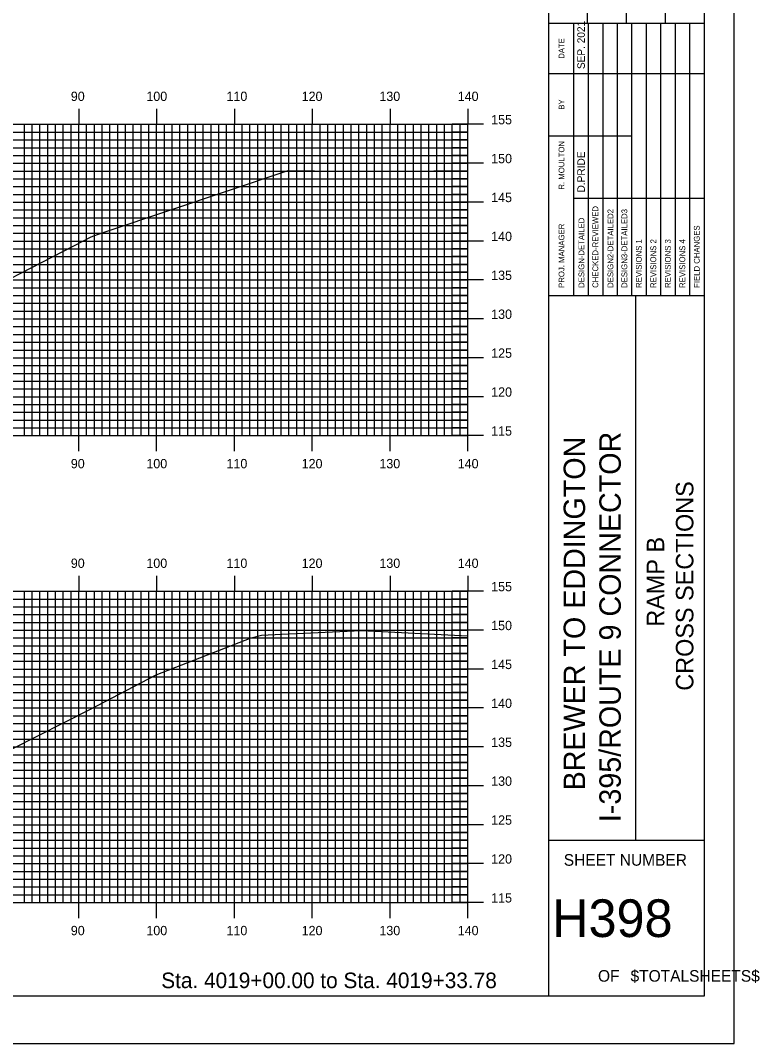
# Model space of a CAD drawing. Extents: x 854902 to 855245, y 364661 to 364881.
# Drawn here: x 855149.8 to 855244.8, y 364661.3 to 364792.7 of the extents above; entities that cross this region are included whole.
import ezdxf

# ---------------------------------------------------------------- set-up
doc = ezdxf.new("R2010")
doc.units = 0
for name, color, linetype in [('BORDER', 7, 'Continuous'), ('H_V ANNOTATION', 7, 'Continuous'), ('MAJOR', 7, 'Continuous'), ('MINOR', 7, 'Continuous'), ('PLOT BOUNDARY', 7, 'Continuous'), ('S_Roadway_Centerline', 7, 'Continuous')]:
    doc.layers.add(name, color=color, linetype=linetype)

msp = doc.modelspace()

# ---------------------------------------------------------------- linework, layer by layer
at = {"layer": 'BORDER'}
for p, q in [((855217.75, 364667.37), (855217.75, 364877.37)), ((855222.75, 364792.38), (855222.75, 364809.67)), ((855227.75, 364792.38), (855227.75, 364809.67)), ((855232.75, 364792.38), (855232.75, 364809.67)), ((855217.75, 364792.38), (855237.75, 364792.38)), ((855217.75, 364757.38), (855237.75, 364757.38)), ((855228.93, 364687.38), (855228.93, 364757.38)), ((855217.75, 364687.38), (855237.75, 364687.38))]:
    msp.add_line(p, q, dxfattribs=at)
msp.add_lwpolyline([(854917.75, 364667.37), (855237.75, 364667.37), (855237.75, 364877.37), (854917.75, 364877.37)], close=True, dxfattribs=at)
for points in [[(855220.98, 364785.88), (855220.98, 364792.38)], [(855222.84, 364757.38), (855222.84, 364792.38)], [(855224.71, 364792.38), (855224.71, 364757.38)], [(855226.57, 364757.38), (855226.57, 364792.38)], [(855228.43, 364757.38), (855228.43, 364792.38)], [(855230.3, 364757.38), (855230.3, 364792.38)], [(855232.16, 364757.38), (855232.16, 364792.38)], [(855234.02, 364757.38), (855234.02, 364792.38)], [(855235.89, 364757.38), (855235.89, 364792.38)], [(855220.98, 364757.38), (855220.98, 364790.96)], [(855217.75, 364785.88), (855237.75, 364785.88)], [(855217.75, 364777.88), (855220.98, 364777.88)], [(855220.98, 364777.88), (855228.43, 364777.88)], [(855220.98, 364769.88), (855237.75, 364769.88)]]:
    msp.add_lwpolyline(points, dxfattribs=at)
at = {"layer": 'MAJOR'}
for p, q in [((855157.35, 364781.37), (855157.35, 364779.37)), ((855167.35, 364781.37), (855167.35, 364779.37)), ((855177.35, 364781.37), (855177.35, 364779.37)), ((855187.35, 364781.37), (855187.35, 364779.37)), ((855197.35, 364781.37), (855197.35, 364779.37)), ((855207.35, 364781.37), (855207.35, 364779.37)), ((854927.35, 364779.37), (855207.35, 364779.37)), ((854927.35, 364779.37), (855207.35, 364779.37)), ((855157.35, 364739.37), (855157.35, 364779.37)), ((855167.35, 364739.37), (855167.35, 364779.37)), ((855177.35, 364739.37), (855177.35, 364779.37)), ((855187.35, 364739.37), (855187.35, 364779.37)), ((855197.35, 364739.37), (855197.35, 364779.37)), ((855209.35, 364779.37), (855205.34, 364779.37)), ((855207.35, 364739.37), (855207.35, 364779.37)), ((855207.35, 364739.37), (855207.35, 364779.37)), ((854927.35, 364774.37), (855207.35, 364774.37)), ((855209.35, 364774.37), (855205.34, 364774.37)), ((854927.35, 364769.37), (855207.35, 364769.37)), ((855209.35, 364769.37), (855205.34, 364769.37)), ((854927.35, 364764.37), (855207.35, 364764.37)), ((855209.35, 364764.37), (855205.34, 364764.37)), ((854927.35, 364759.37), (855207.35, 364759.37)), ((855209.35, 364759.37), (855205.34, 364759.37)), ((854927.35, 364754.37), (855207.35, 364754.37)), ((855209.35, 364754.37), (855205.34, 364754.37)), ((854927.35, 364749.37), (855207.35, 364749.37)), ((855209.35, 364749.37), (855205.34, 364749.37)), ((854927.35, 364744.37), (855207.35, 364744.37)), ((855209.35, 364744.37), (855205.34, 364744.37)), ((854927.35, 364739.37), (855207.35, 364739.37)), ((854927.35, 364739.37), (855207.35, 364739.37)), ((855157.35, 364737.37), (855157.35, 364739.37)), ((855167.35, 364737.37), (855167.35, 364739.37)), ((855177.35, 364737.37), (855177.35, 364739.37)), ((855187.35, 364737.37), (855187.35, 364739.37)), ((855197.35, 364737.37), (855197.35, 364739.37)), ((855209.35, 364739.37), (855205.34, 364739.37)), ((855207.35, 364737.37), (855207.35, 364739.37)), ((855157.35, 364721.37), (855157.35, 364719.37)), ((855167.35, 364721.37), (855167.35, 364719.37)), ((855177.35, 364721.37), (855177.35, 364719.37)), ((855187.35, 364721.37), (855187.35, 364719.37)), ((855197.35, 364721.37), (855197.35, 364719.37)), ((855207.35, 364721.37), (855207.35, 364719.37)), ((854927.35, 364719.37), (855207.35, 364719.37)), ((854927.35, 364719.37), (855207.35, 364719.37)), ((855157.35, 364679.37), (855157.35, 364719.37)), ((855167.35, 364679.37), (855167.35, 364719.37)), ((855177.35, 364679.37), (855177.35, 364719.37)), ((855187.35, 364679.37), (855187.35, 364719.37)), ((855197.35, 364679.37), (855197.35, 364719.37)), ((855209.35, 364719.37), (855205.34, 364719.37)), ((855207.35, 364679.37), (855207.35, 364719.37)), ((855207.35, 364679.37), (855207.35, 364719.37)), ((854927.35, 364714.37), (855207.35, 364714.37)), ((855209.35, 364714.37), (855205.34, 364714.37)), ((854927.35, 364709.37), (855207.35, 364709.37)), ((855209.35, 364709.37), (855205.34, 364709.37)), ((854927.35, 364704.37), (855207.35, 364704.37)), ((855209.35, 364704.37), (855205.34, 364704.37)), ((854927.35, 364699.37), (855207.35, 364699.37)), ((855209.35, 364699.37), (855205.34, 364699.37)), ((854927.35, 364694.37), (855207.35, 364694.37)), ((855209.35, 364694.37), (855205.34, 364694.37)), ((854927.35, 364689.37), (855207.35, 364689.37)), ((855209.35, 364689.37), (855205.34, 364689.37)), ((854927.35, 364684.37), (855207.35, 364684.37)), ((855209.35, 364684.37), (855205.34, 364684.37)), ((854927.35, 364679.37), (855207.35, 364679.37)), ((854927.35, 364679.37), (855207.35, 364679.37)), ((855157.35, 364677.37), (855157.35, 364679.37)), ((855167.35, 364677.37), (855167.35, 364679.37)), ((855177.35, 364677.37), (855177.35, 364679.37)), ((855187.35, 364677.37), (855187.35, 364679.37)), ((855197.35, 364677.37), (855197.35, 364679.37)), ((855209.35, 364679.37), (855205.34, 364679.37)), ((855207.35, 364677.37), (855207.35, 364679.37))]:
    msp.add_line(p, q, dxfattribs=at)
at = {"layer": 'MINOR'}
for p, q in [((855150.35, 364739.37), (855150.35, 364779.37)), ((855151.35, 364739.37), (855151.35, 364779.37)), ((855152.35, 364739.37), (855152.35, 364779.37)), ((855153.35, 364739.37), (855153.35, 364779.37)), ((855154.35, 364739.37), (855154.35, 364779.37)), ((855155.35, 364739.37), (855155.35, 364779.37)), ((855156.35, 364739.37), (855156.35, 364779.37)), ((855158.35, 364739.37), (855158.35, 364779.37)), ((855159.35, 364739.37), (855159.35, 364779.37)), ((855160.35, 364739.37), (855160.35, 364779.37)), ((855161.35, 364739.37), (855161.35, 364779.37)), ((855162.35, 364739.37), (855162.35, 364779.37)), ((855163.35, 364739.37), (855163.35, 364779.37)), ((855164.35, 364739.37), (855164.35, 364779.37)), ((855165.35, 364739.37), (855165.35, 364779.37)), ((855166.35, 364739.37), (855166.35, 364779.37)), ((855168.35, 364739.37), (855168.35, 364779.37)), ((855169.35, 364739.37), (855169.35, 364779.37)), ((855170.35, 364739.37), (855170.35, 364779.37)), ((855171.35, 364739.37), (855171.35, 364779.37)), ((855172.35, 364739.37), (855172.35, 364779.37)), ((855173.35, 364739.37), (855173.35, 364779.37)), ((855174.35, 364739.37), (855174.35, 364779.37)), ((855175.35, 364739.37), (855175.35, 364779.37)), ((855176.35, 364739.37), (855176.35, 364779.37)), ((855178.35, 364739.37), (855178.35, 364779.37)), ((855179.35, 364739.37), (855179.35, 364779.37)), ((855180.35, 364739.37), (855180.35, 364779.37)), ((855181.35, 364739.37), (855181.35, 364779.37)), ((855182.35, 364739.37), (855182.35, 364779.37)), ((855183.35, 364739.37), (855183.35, 364779.37)), ((855184.35, 364739.37), (855184.35, 364779.37)), ((855185.35, 364739.37), (855185.35, 364779.37)), ((855186.35, 364739.37), (855186.35, 364779.37)), ((855188.35, 364739.37), (855188.35, 364779.37)), ((855189.35, 364739.37), (855189.35, 364779.37)), ((855190.35, 364739.37), (855190.35, 364779.37)), ((855191.35, 364739.37), (855191.35, 364779.37)), ((855192.35, 364739.37), (855192.35, 364779.37)), ((855193.35, 364739.37), (855193.35, 364779.37)), ((855194.35, 364739.37), (855194.35, 364779.37)), ((855195.35, 364739.37), (855195.35, 364779.37)), ((855196.35, 364739.37), (855196.35, 364779.37)), ((855198.35, 364739.37), (855198.35, 364779.37)), ((855199.35, 364739.37), (855199.35, 364779.37)), ((855200.35, 364739.37), (855200.35, 364779.37)), ((855201.35, 364739.37), (855201.35, 364779.37)), ((855202.35, 364739.37), (855202.35, 364779.37)), ((855203.35, 364739.37), (855203.35, 364779.37)), ((855204.35, 364739.37), (855204.35, 364779.37)), ((855205.35, 364739.37), (855205.35, 364779.37)), ((855206.35, 364739.37), (855206.35, 364779.37)), ((854927.35, 364778.37), (855207.35, 364778.37)), ((855207.35, 364778.37), (855205.34, 364778.37)), ((854927.35, 364777.37), (855207.35, 364777.37)), ((854927.35, 364776.37), (855207.35, 364776.37)), ((855207.35, 364777.37), (855205.34, 364777.37)), ((855207.35, 364776.37), (855205.34, 364776.37)), ((854927.35, 364775.37), (855207.35, 364775.37)), ((855207.35, 364775.37), (855205.34, 364775.37)), ((854927.35, 364773.37), (855207.35, 364773.37)), ((854927.35, 364772.37), (855207.35, 364772.37)), ((855207.35, 364773.37), (855205.34, 364773.37)), ((855207.35, 364772.37), (855205.34, 364772.37)), ((854927.35, 364771.37), (855207.35, 364771.37)), ((855207.35, 364771.37), (855205.34, 364771.37)), ((854927.35, 364770.37), (855207.35, 364770.37)), ((855207.35, 364770.37), (855205.34, 364770.37)), ((854927.35, 364768.37), (855207.35, 364768.37)), ((855207.35, 364768.37), (855205.34, 364768.37)), ((854927.35, 364767.37), (855207.35, 364767.37)), ((855207.35, 364767.37), (855205.34, 364767.37)), ((854927.35, 364766.37), (855207.35, 364766.37)), ((855207.35, 364766.37), (855205.34, 364766.37)), ((854927.35, 364765.37), (855207.35, 364765.37)), ((855207.35, 364765.37), (855205.34, 364765.37)), ((854927.35, 364763.37), (855207.35, 364763.37)), ((855207.35, 364763.37), (855205.34, 364763.37)), ((854927.35, 364762.37), (855207.35, 364762.37)), ((855207.35, 364762.37), (855205.34, 364762.37)), ((854927.35, 364761.37), (855207.35, 364761.37)), ((855207.35, 364761.37), (855205.34, 364761.37)), ((854927.35, 364760.37), (855207.35, 364760.37)), ((855207.35, 364760.37), (855205.34, 364760.37)), ((854927.35, 364758.37), (855207.35, 364758.37)), ((855207.35, 364758.37), (855205.34, 364758.37)), ((854927.35, 364757.37), (855207.35, 364757.37)), ((855207.35, 364757.37), (855205.34, 364757.37)), ((854927.35, 364756.37), (855207.35, 364756.37)), ((854927.35, 364755.37), (855207.35, 364755.37)), ((855207.35, 364756.37), (855205.34, 364756.37)), ((855207.35, 364755.37), (855205.34, 364755.37)), ((854927.35, 364753.37), (855207.35, 364753.37)), ((855207.35, 364753.37), (855205.34, 364753.37)), ((854927.35, 364752.37), (855207.35, 364752.37)), ((854927.35, 364751.37), (855207.35, 364751.37)), ((855207.35, 364752.37), (855205.34, 364752.37)), ((855207.35, 364751.37), (855205.34, 364751.37)), ((854927.35, 364750.37), (855207.35, 364750.37)), ((855207.35, 364750.37), (855205.34, 364750.37)), ((854927.35, 364748.37), (855207.35, 364748.37)), ((854927.35, 364747.37), (855207.35, 364747.37)), ((855207.35, 364748.37), (855205.34, 364748.37)), ((855207.35, 364747.37), (855205.34, 364747.37)), ((854927.35, 364746.37), (855207.35, 364746.37)), ((855207.35, 364746.37), (855205.34, 364746.37)), ((854927.35, 364745.37), (855207.35, 364745.37)), ((855207.35, 364745.37), (855205.34, 364745.37)), ((854927.35, 364743.37), (855207.35, 364743.37)), ((855207.35, 364743.37), (855205.34, 364743.37)), ((854927.35, 364742.37), (855207.35, 364742.37)), ((855207.35, 364742.37), (855205.34, 364742.37)), ((854927.35, 364741.37), (855207.35, 364741.37)), ((855207.35, 364741.37), (855205.34, 364741.37)), ((854927.35, 364740.37), (855207.35, 364740.37)), ((855207.35, 364740.37), (855205.34, 364740.37)), ((854927.35, 364718.37), (855207.35, 364718.37)), ((855150.35, 364679.37), (855150.35, 364719.37)), ((855151.35, 364679.37), (855151.35, 364719.37)), ((855152.35, 364679.37), (855152.35, 364719.37)), ((855153.35, 364679.37), (855153.35, 364719.37)), ((855154.35, 364679.37), (855154.35, 364719.37)), ((855155.35, 364679.37), (855155.35, 364719.37)), ((855156.35, 364679.37), (855156.35, 364719.37)), ((855158.35, 364679.37), (855158.35, 364719.37)), ((855159.35, 364679.37), (855159.35, 364719.37)), ((855160.35, 364679.37), (855160.35, 364719.37)), ((855161.35, 364679.37), (855161.35, 364719.37)), ((855162.35, 364679.37), (855162.35, 364719.37)), ((855163.35, 364679.37), (855163.35, 364719.37)), ((855164.35, 364679.37), (855164.35, 364719.37)), ((855165.35, 364679.37), (855165.35, 364719.37)), ((855166.35, 364679.37), (855166.35, 364719.37)), ((855168.35, 364679.37), (855168.35, 364719.37)), ((855169.35, 364679.37), (855169.35, 364719.37)), ((855170.35, 364679.37), (855170.35, 364719.37)), ((855171.35, 364679.37), (855171.35, 364719.37)), ((855172.35, 364679.37), (855172.35, 364719.37)), ((855173.35, 364679.37), (855173.35, 364719.37)), ((855174.35, 364679.37), (855174.35, 364719.37)), ((855175.35, 364679.37), (855175.35, 364719.37)), ((855176.35, 364679.37), (855176.35, 364719.37)), ((855178.35, 364679.37), (855178.35, 364719.37)), ((855179.35, 364679.37), (855179.35, 364719.37)), ((855180.35, 364679.37), (855180.35, 364719.37)), ((855181.35, 364679.37), (855181.35, 364719.37)), ((855182.35, 364679.37), (855182.35, 364719.37)), ((855183.35, 364679.37), (855183.35, 364719.37)), ((855184.35, 364679.37), (855184.35, 364719.37)), ((855185.35, 364679.37), (855185.35, 364719.37)), ((855186.35, 364679.37), (855186.35, 364719.37)), ((855188.35, 364679.37), (855188.35, 364719.37)), ((855189.35, 364679.37), (855189.35, 364719.37)), ((855190.35, 364679.37), (855190.35, 364719.37)), ((855191.35, 364679.37), (855191.35, 364719.37)), ((855192.35, 364679.37), (855192.35, 364719.37)), ((855193.35, 364679.37), (855193.35, 364719.37)), ((855194.35, 364679.37), (855194.35, 364719.37)), ((855195.35, 364679.37), (855195.35, 364719.37)), ((855196.35, 364679.37), (855196.35, 364719.37)), ((855198.35, 364679.37), (855198.35, 364719.37)), ((855199.35, 364679.37), (855199.35, 364719.37)), ((855200.35, 364679.37), (855200.35, 364719.37)), ((855201.35, 364679.37), (855201.35, 364719.37)), ((855202.35, 364679.37), (855202.35, 364719.37)), ((855203.35, 364679.37), (855203.35, 364719.37)), ((855204.35, 364679.37), (855204.35, 364719.37)), ((855207.35, 364718.37), (855205.34, 364718.37)), ((855205.35, 364679.37), (855205.35, 364719.37)), ((855206.35, 364679.37), (855206.35, 364719.37)), ((854927.35, 364717.37), (855207.35, 364717.37)), ((855207.35, 364717.37), (855205.34, 364717.37)), ((854927.35, 364716.37), (855207.35, 364716.37)), ((855207.35, 364716.37), (855205.34, 364716.37)), ((854927.35, 364715.37), (855207.35, 364715.37)), ((855207.35, 364715.37), (855205.34, 364715.37)), ((854927.35, 364713.37), (855207.35, 364713.37)), ((855207.35, 364713.37), (855205.34, 364713.37)), ((854927.35, 364712.37), (855207.35, 364712.37)), ((855207.35, 364712.37), (855205.34, 364712.37)), ((854927.35, 364711.37), (855207.35, 364711.37)), ((855207.35, 364711.37), (855205.34, 364711.37)), ((854927.35, 364710.37), (855207.35, 364710.37)), ((855207.35, 364710.37), (855205.34, 364710.37)), ((854927.35, 364708.37), (855207.35, 364708.37)), ((855207.35, 364708.37), (855205.34, 364708.37)), ((854927.35, 364707.37), (855207.35, 364707.37)), ((855207.35, 364707.37), (855205.34, 364707.37)), ((854927.35, 364706.37), (855207.35, 364706.37)), ((854927.35, 364705.37), (855207.35, 364705.37)), ((855207.35, 364706.37), (855205.34, 364706.37)), ((855207.35, 364705.37), (855205.34, 364705.37)), ((854927.35, 364703.37), (855207.35, 364703.37)), ((855207.35, 364703.37), (855205.34, 364703.37)), ((854927.35, 364702.37), (855207.35, 364702.37)), ((854927.35, 364701.37), (855207.35, 364701.37)), ((855207.35, 364702.37), (855205.34, 364702.37)), ((855207.35, 364701.37), (855205.34, 364701.37)), ((854927.35, 364700.37), (855207.35, 364700.37)), ((855207.35, 364700.37), (855205.34, 364700.37)), ((854927.35, 364698.37), (855207.35, 364698.37)), ((854927.35, 364697.37), (855207.35, 364697.37)), ((855207.35, 364698.37), (855205.34, 364698.37)), ((855207.35, 364697.37), (855205.34, 364697.37)), ((854927.35, 364696.37), (855207.35, 364696.37)), ((855207.35, 364696.37), (855205.34, 364696.37)), ((854927.35, 364695.37), (855207.35, 364695.37)), ((855207.35, 364695.37), (855205.34, 364695.37)), ((854927.35, 364693.37), (855207.35, 364693.37)), ((855207.35, 364693.37), (855205.34, 364693.37)), ((854927.35, 364692.37), (855207.35, 364692.37)), ((855207.35, 364692.37), (855205.34, 364692.37)), ((854927.35, 364691.37), (855207.35, 364691.37)), ((855207.35, 364691.37), (855205.34, 364691.37)), ((854927.35, 364690.37), (855207.35, 364690.37)), ((855207.35, 364690.37), (855205.34, 364690.37)), ((854927.35, 364688.37), (855207.35, 364688.37)), ((855207.35, 364688.37), (855205.34, 364688.37)), ((854927.35, 364687.37), (855207.35, 364687.37)), ((855207.35, 364687.37), (855205.34, 364687.37)), ((854927.35, 364686.37), (855207.35, 364686.37)), ((855207.35, 364686.37), (855205.34, 364686.37)), ((854927.35, 364685.37), (855207.35, 364685.37)), ((855207.35, 364685.37), (855205.34, 364685.37)), ((854927.35, 364683.37), (855207.35, 364683.37)), ((855207.35, 364683.37), (855205.34, 364683.37)), ((854927.35, 364682.37), (855207.35, 364682.37)), ((855207.35, 364682.37), (855205.34, 364682.37)), ((854927.35, 364681.37), (855207.35, 364681.37)), ((854927.35, 364680.37), (855207.35, 364680.37)), ((855207.35, 364681.37), (855205.34, 364681.37)), ((855207.35, 364680.37), (855205.34, 364680.37))]:
    msp.add_line(p, q, dxfattribs=at)
at = {"layer": 'PLOT BOUNDARY'}
msp.add_lwpolyline([(854901.56, 364661.25), (855241.56, 364661.25), (855241.56, 364881.25), (854901.56, 364881.25)], close=True, dxfattribs=at)
at = {"layer": 'S_Roadway_Centerline'}
for points in [[(855140.39, 364755.35), (855158.02, 364764.44), (855158.85, 364764.85), (855159.15, 364764.99), (855160.99, 364765.65), (855184.26, 364773.44), (855191.08, 364773.34), (855198.6, 364773.33), (855207.35, 364773.44)], [(855148.79, 364699.11), (855158.78, 364704.18), (855167.28, 364708.65), (855179.5, 364713.37), (855180.82, 364713.73), (855183.43, 364713.85), (855193.68, 364714.33), (855207.35, 364713.64)]]:
    msp.add_lwpolyline(points, dxfattribs=at)

# ---------------------------------------------------------------- texts
at = {"layer": 'BORDER'}
for s, height, p in [('SEP. 2021', 0.969, (855222.39, 364786.47)), ('DATE', 0.743, (855219.76, 364787.79)), ('BY', 0.743, (855219.76, 364781.25)), ('R. MOULTON', 0.745, (855219.76, 364770.98)), ('D.PRIDE', 0.969, (855222.39, 364770.62)), ('CHECKED-REVIEWED', 0.7455, (855224.11, 364758.35)), ('DESIGN2-DETAILED2', 0.7455, (855226.05, 364758.35)), ('DESIGN3-DETAILED3', 0.7455, (855227.84, 364758.35)), ('DESIGN-DETAILED', 0.7455, (855222.32, 364758.35)), ('PROJ. MANAGER', 0.7455, (855219.76, 364758.35)), ('FIELD CHANGES', 0.7455, (855237.15, 364758.35)), ('REVISIONS 1', 0.7455, (855229.7, 364758.35)), ('REVISIONS 2', 0.7455, (855231.56, 364758.35)), ('REVISIONS 3', 0.7455, (855233.43, 364758.35)), ('REVISIONS 4', 0.7455, (855235.29, 364758.35)), ('I-395/ROUTE 9 CONNECTOR', 2.7557, (855227.01, 364689.7)), ('BREWER TO EDDINGTON', 2.7557, (855222.42, 364693.78)), ('CROSS SECTIONS', 2.25, (855236.34, 364706.59)), ('RAMP B', 2.25, (855232.59, 364714.82))]:
    msp.add_text(s, height=height, rotation=90, dxfattribs=at).set_placement(p)
for s, height, p in [('SHEET NUMBER', 1.4905, (855219.68, 364684.1)), ('H398', 4.839, (855218.19, 364674.94)), ('OF', 1.491, (855224.08, 364669.2)), ('$TOTALSHEETS$', 1.4905, (855228.26, 364669.2))]:
    msp.add_text(s, height=height, dxfattribs=at).set_placement(p)
at = {"layer": 'H_V ANNOTATION'}
for s, height, p in [('90', 1.2, (855156.32, 364782.37)), ('100', 1.2, (855166.03, 364782.37)), ('110', 1.2, (855176.33, 364782.37)), ('120', 1.2, (855185.99, 364782.37)), ('130', 1.2, (855195.98, 364782.37)), ('140', 1.2, (855206.05, 364782.37)), ('155', 1.2, (855210.35, 364779.37)), ('150', 1.2, (855210.35, 364774.37)), ('145', 1.2, (855210.35, 364769.37)), ('140', 1.2, (855210.35, 364764.37)), ('135', 1.2, (855210.35, 364759.37)), ('130', 1.2, (855210.35, 364754.37)), ('125', 1.2, (855210.35, 364749.37)), ('120', 1.2, (855210.35, 364744.37)), ('115', 1.2, (855210.35, 364739.37)), ('90', 1.2, (855156.32, 364735.17)), ('100', 1.2, (855166.03, 364735.17)), ('110', 1.2, (855176.33, 364735.17)), ('120', 1.2, (855185.99, 364735.17)), ('130', 1.2, (855195.98, 364735.17)), ('140', 1.2, (855206.05, 364735.17)), ('90', 1.2, (855156.32, 364722.37)), ('100', 1.2, (855166.03, 364722.37)), ('110', 1.2, (855176.33, 364722.37)), ('120', 1.2, (855185.99, 364722.37)), ('130', 1.2, (855195.98, 364722.37)), ('140', 1.2, (855206.05, 364722.37)), ('155', 1.2, (855210.35, 364719.37)), ('150', 1.2, (855210.35, 364714.37)), ('145', 1.2, (855210.35, 364709.37)), ('140', 1.2, (855210.35, 364704.37)), ('135', 1.2, (855210.35, 364699.37)), ('130', 1.2, (855210.35, 364694.37)), ('125', 1.2, (855210.35, 364689.37)), ('120', 1.2, (855210.35, 364684.37)), ('115', 1.2, (855210.35, 364679.37)), ('90', 1.2, (855156.32, 364675.17)), ('100', 1.2, (855166.03, 364675.17)), ('110', 1.2, (855176.33, 364675.17)), ('120', 1.2, (855185.99, 364675.17)), ('130', 1.2, (855195.98, 364675.17)), ('140', 1.2, (855206.05, 364675.17)), ('Sta. 4019+00.00 to Sta. 4019+33.78', 2.0004, (855167.94, 364668.37))]:
    msp.add_text(s, height=height, dxfattribs=at).set_placement(p)

doc.saveas('drawing.dxf')
